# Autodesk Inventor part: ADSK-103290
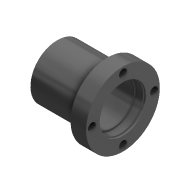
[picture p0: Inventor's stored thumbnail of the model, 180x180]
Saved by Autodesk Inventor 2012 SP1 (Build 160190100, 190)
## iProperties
Shininess: 0.0
Created: 2000-04
Part Number: ADSK-103290
Document SubType Name: Modeling
Stock Number: ADSK-103290
Density: 1 g/cm^3
Material: Default
Density: 0.0
Volumn: 0.0
Area: 0.0
PropertySet Name: Model Information
Control State: 0
Checked Out: False
Master: False
Author: gao
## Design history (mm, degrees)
node "Revolution1" dims "d16" = 360 deg
  sketch "Sketch1"
    geometry: L1 (-80.275, 14.814)-(-80.275, 28.206); L2 (43.55, 28.714)-(84.825, 28.714); L3 (84.825, 28.714)-(84.825, 60.464); L4 (84.825, 60.464)-(135.625, 60.464); L5 (135.625, 60.464)-(135.625, 14.814); L6 (-75.195, 14.814)-(-80.275, 14.814); L7 (102.402, 9.664)-(-47.052, 9.664); L8 (-14.053, -60.186)-(9.95, -60.186); L9 (130.545, 14.814)-(130.545, 19.824); L10 (130.545, 19.824)-(126.405, 19.824); L11 (126.405, 19.824)-(126.405, 14.814); L12 (135.625, 14.814)-(130.545, 14.814); L13 (-75.195, 14.814)-(-75.195, 19.824); L14 (-75.195, 19.824)-(-71.055, 19.824); L15 (-71.055, 19.824)-(-71.055, 14.814); L16 (-71.055, 14.814)-(-47.052, 14.814); L17 (-47.052, 14.814)-(-47.052, 9.664); L18 (102.402, 9.664)-(102.402, 14.814); L19 (102.402, 14.814)-(126.405, 14.814); L20 (-80.275, 28.206)-(43.55, 28.206); L21 (43.55, 28.206)-(43.55, 28.714)
    constraints: 42 end point, 10 perpendicular, 8 parallel, 4 equal length, 1 vertical
    dimensions: "d0" = 120.65 distance between parallel lines of L4 L8; "d1" = 88.9 distance between parallel lines of L8 L2; "d2" = 74.99985 distance between parallel lines of L8 L6; "d3" = 69.85 distance between parallel lines of L8 L7; "d8" = 5.08 distance of L5.end L9.start; "d9" = 4.1402 distance of L9.end L10.end; "d10" = 24.003 distance between parallel lines of L11 L18; "d11" = 74.99985 distance from line of L8 L5.end (= d2); "d12" = 80.01 distance from line of L8 L9.end; "d13" = 80.01 vertical distance of L8.start L13.end (= d12); "d14" = 74.99985 distance from line of L8.start L16 (= d2); "d15" = 74.99985 distance between parallel lines of L8 L19 (= d2); "d62" = 165.1 distance between parallel lines of L3 L1; "d63" = 41.275 distance of L2.start L2.end; "d64" = 88.392 distance between parallel lines of L8 L20; "d67" = 50.8 distance of L3.end L4.end
node "Chamfer2" dims "d49" = 1.016, "d50" = 1.016, "d68" = 45 deg
node "Hole4" dims "d53" = 16.51, "d54" = 25.4, "d55" = 15.875, "d56" = 60 deg, "d57" = 19.05, "d58" = 118 deg
  sketch "Sketch5" dims "d52" = 203.2
    geometry: C1 r 76.016 at (0, 0) reference; 2 further points
    constraints: 1 coincident, 1 vertical alignment, 2 other
node "Circular Pattern4" dims "d59" = 40, "d61" = 90 deg
node "Chamfer3" dims "d65" = 1.524, "d66" = 1.524, "d69" = 45 deg
body "Solid1"
other parameters: "d4" = 74.99985 (= d2), "d51" = 203.2 (derived)
